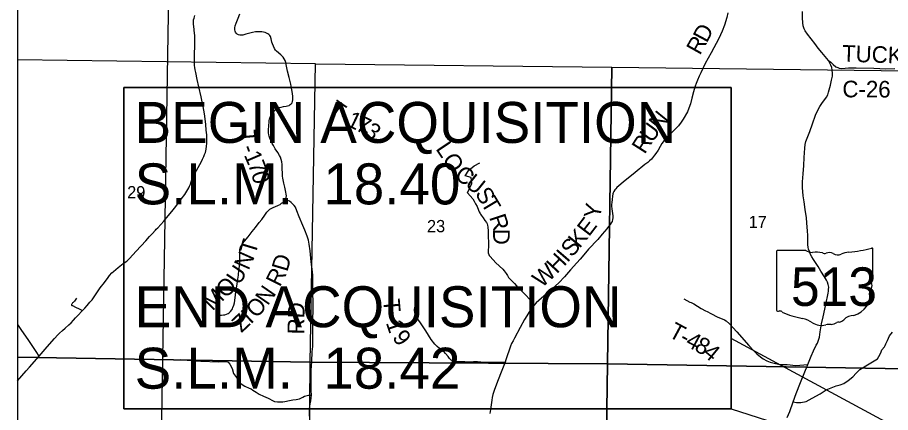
# Model space of a CAD drawing. Extents: x 0 to 34, y 0 to 22.
# Drawn here: x 2.1 to 5.085, y 17.307 to 18.658 of the extents above; entities that cross this region are included whole.
import ezdxf

# ---------------------------------------------------------------- set-up
doc = ezdxf.new("R2010")
doc.units = 0
for name, color, linetype in [('GM_X_Corporation', 7, 'Continuous'), ('GM_X_County_Road', 7, 'Continuous'), ('GM_X_County_Road_Text', 7, 'Continuous'), ('GM_X_Section_Text', 7, 'Continuous'), ('GM_X_State_Location', 7, 'Continuous'), ('GM_X_State_Route', 7, 'Continuous'), ('GM_X_State_Shield', 7, 'Continuous'), ('GM_X_Township_Road', 7, 'Continuous'), ('GM_X_Township_Road_Text', 7, 'Continuous'), ('GM_X_Township_Text', 7, 'Continuous'), ('SH_Data', 7, 'Continuous'), ('SH_Text', 7, 'Continuous')]:
    doc.layers.add(name, color=color, linetype=linetype)

msp = doc.modelspace()

# ---------------------------------------------------------------- linework, layer by layer
at = {"layer": 'GM_X_Corporation'}
for points in [[(2.1, 18.5128), (2.1, 17.4968), (3.1011, 17.4796), (3.1188, 18.4989)], [(3.1188, 18.4989), (4.1319, 18.4883), (4.1176, 17.4733), (3.1011, 17.4796)], [(4.1319, 18.4883), (5.1454, 18.4748), (5.1353, 17.4571), (4.1176, 17.4733)], [(2.1, 17.4968), (2.1, 16.4774), (3.0928, 16.4681), (3.1011, 17.4796)], [(3.1011, 17.4796), (4.1176, 17.4733), (4.1025, 16.4586), (3.0928, 16.4681)], [(4.1176, 17.4733), (5.1353, 17.4571), (5.122, 16.4496), (4.1025, 16.4586)]]:
    msp.add_lwpolyline(points, close=True, dxfattribs=at)
at = {"layer": 'GM_X_County_Road'}
for points in [[(2.5794, 17.939), (2.5999, 17.9616), (2.6041, 17.9664), (2.6281, 17.995), (2.6416, 18.0114), (2.6602, 18.0362), (2.6722, 18.0526), (2.6825, 18.0697), (2.6857, 18.075), (2.6883, 18.081), (2.6913, 18.0878), (2.6931, 18.0926), (2.695, 18.099), (2.697, 18.1066), (2.6991, 18.1112), (2.7017, 18.1167), (2.7178, 18.1452), (2.7237, 18.1556), (2.7277, 18.1629), (2.733, 18.1733), (2.7373, 18.1823), (2.7399, 18.189), (2.7425, 18.1966), (2.7449, 18.2073), (2.7466, 18.2183), (2.7475, 18.2264), (2.7474, 18.234), (2.7475, 18.2479), (2.7471, 18.2568), (2.7457, 18.2729), (2.7437, 18.2924), (2.7414, 18.3118), (2.7391, 18.3278), (2.7348, 18.3536), (2.7278, 18.3868), (2.7203, 18.4207), (2.7143, 18.4462), (2.7093, 18.4701), (2.7078, 18.4784), (2.7065, 18.4862), (2.7057, 18.4936), (2.7049, 18.5029), (2.7052, 18.5157), (2.7054, 18.5281), (2.7058, 18.5404), (2.7067, 18.5523), (2.7069, 18.5698), (2.7066, 18.5827), (2.7059, 18.5976), (2.7052, 18.6033), (2.7028, 18.6285), (2.7021, 18.6342), (2.7019, 18.6387), (2.7019, 18.6437), (2.7024, 18.6494), (2.7038, 18.6558), (2.7066, 18.6645)], [(4.5288, 18.6738), (4.5247, 18.6574), (4.517, 18.6315), (4.5092, 18.6111), (4.498, 18.5853), (4.4716, 18.5367), (4.4514, 18.5004), (4.4358, 18.469), (4.4306, 18.4575), (4.4246, 18.4438), (4.4201, 18.4323), (4.4168, 18.4225), (4.4113, 18.4032), (4.4058, 18.3816), (4.4007, 18.3629), (4.3954, 18.3476), (4.3903, 18.3356), (4.376, 18.3105), (4.3696, 18.3), (4.3597, 18.2873), (4.3513, 18.2783), (4.3367, 18.264), (4.3175, 18.2459), (4.3105, 18.237), (4.3033, 18.2265), (4.2969, 18.2162), (4.2899, 18.2047), (4.2826, 18.1929), (4.2784, 18.1866), (4.2676, 18.1735), (4.2612, 18.1675), (4.2552, 18.1625), (4.2451, 18.1547), (4.2118, 18.1281), (4.1934, 18.1135), (4.1781, 18.1009), (4.1495, 18.0763), (4.1461, 18.0725), (4.1422, 18.0682), (4.1392, 18.0634), (4.1369, 18.0581), (4.136, 18.0546), (4.1347, 18.0473), (4.1331, 18.0356), (4.1318, 18.0251), (4.1314, 18.0179), (4.1314, 18.0126), (4.1322, 18.0032), (4.1344, 17.9874), (4.135, 17.9801), (4.1353, 17.9731), (4.1344, 17.9668), (4.1326, 17.9607), (4.1303, 17.9558), (4.1266, 17.9506), (4.1209, 17.9428), (4.1146, 17.9353), (4.0988, 17.9168), (4.0836, 17.8992), (4.0526, 17.8655), (4.0415, 17.8527), (4.0233, 17.8317), (4.0125, 17.8196), (3.991, 17.7949), (3.9703, 17.7707), (3.9508, 17.7512), (3.9287, 17.7314), (3.9076, 17.7124), (3.8916, 17.6982), (3.8822, 17.6898), (3.8736, 17.6821), (3.8658, 17.6734), (3.8603, 17.6662), (3.8552, 17.6592), (3.8486, 17.6495), (3.8412, 17.6374), (3.834, 17.6258), (3.8182, 17.5981), (3.7995, 17.5617), (3.7945, 17.552), (3.789, 17.5428), (3.7853, 17.5342), (3.7695, 17.4874), (3.7668, 17.4795), (3.7561, 17.4506), (3.7416, 17.4136), (3.7294, 17.3831), (3.7253, 17.3692), (3.723, 17.3587), (3.7213, 17.3498), (3.7171, 17.3181), (3.715, 17.3038)], [(4.8728, 18.5108), (4.881, 18.5054), (4.8889, 18.4975), (4.8974, 18.4895), (4.9044, 18.4866), (4.9096, 18.4847), (4.9164, 18.4838), (4.9293, 18.485), (4.9416, 18.4856), (4.9668, 18.4855), (5.0278, 18.4839), (5.048, 18.4834), (5.0692, 18.4821), (5.0991, 18.4833)], [(2.1, 17.4156), (2.1298, 17.4495), (2.1411, 17.4622), (2.174, 17.5004), (2.1813, 17.5085), (2.2019, 17.5324), (2.2261, 17.56), (2.2382, 17.5733), (2.2438, 17.5788), (2.254, 17.5881), (2.2631, 17.5962), (2.2756, 17.6074), (2.2832, 17.6145), (2.2914, 17.6227), (2.2989, 17.6307), (2.3068, 17.6391), (2.3215, 17.6547), (2.3228, 17.6563), (2.33, 17.6641), (2.3387, 17.6736), (2.3478, 17.6841), (2.355, 17.693), (2.3733, 17.7197), (2.3779, 17.7263), (2.383, 17.7333), (2.3973, 17.7518), (2.41, 17.7695), (2.4152, 17.7762), (2.4225, 17.7844), (2.428, 17.7897), (2.4362, 17.7963), (2.4448, 17.8031), (2.4619, 17.8163), (2.4734, 17.8252), (2.4829, 17.8339), (2.5063, 17.8586), (2.5384, 17.8944), (2.5519, 17.9088), (2.5602, 17.9181), (2.5724, 17.9312), (2.5746, 17.9338), (2.5794, 17.939)]]:
    msp.add_lwpolyline(points, dxfattribs=at)
at = {"layer": 'GM_X_State_Route'}
msp.add_lwpolyline([(4.7319, 17.2902), (4.7401, 17.3107), (4.7518, 17.3441), (4.7623, 17.372), (4.7769, 17.4097), (4.8024, 17.4712), (4.8133, 17.4995), (4.8216, 17.5186), (4.8311, 17.5373), (4.8347, 17.5449), (4.8385, 17.5545), (4.8415, 17.5646), (4.8433, 17.5741), (4.8443, 17.5827), (4.8491, 17.6101), (4.8545, 17.6342), (4.8637, 17.6765), (4.8713, 17.7153), (4.8724, 17.7218), (4.8732, 17.7284), (4.8735, 17.7362), (4.8718, 17.7453), (4.8693, 17.7529), (4.8662, 17.76), (4.8589, 17.7713), (4.8466, 17.7903), (4.837, 17.806), (4.8213, 17.8301), (4.8161, 17.8394), (4.8113, 17.8481), (4.8076, 17.8573), (4.8047, 17.866), (4.8034, 17.8723), (4.8023, 17.881), (4.8019, 17.8913), (4.8021, 17.9131), (4.8014, 17.9277), (4.7989, 17.9562), (4.7978, 17.973), (4.7931, 18.0019), (4.7898, 18.027), (4.7862, 18.0482), (4.784, 18.077), (4.7839, 18.0959), (4.7858, 18.1232), (4.7883, 18.1521), (4.79, 18.1786), (4.7915, 18.2111), (4.7931, 18.2241), (4.7955, 18.2341), (4.8084, 18.2682), (4.8176, 18.2942), (4.8287, 18.3239), (4.8356, 18.3386), (4.8426, 18.3536), (4.8502, 18.3642), (4.8662, 18.3852), (4.8701, 18.3936), (4.8729, 18.4028), (4.8792, 18.4262), (4.8834, 18.4429), (4.8861, 18.4569), (4.8861, 18.4672), (4.8851, 18.4781), (4.8839, 18.4867), (4.8809, 18.495), (4.8728, 18.5108), (4.8495, 18.5378), (4.8377, 18.5525), (4.8257, 18.5682), (4.8011, 18.6001), (4.7933, 18.6118), (4.789, 18.6193), (4.7857, 18.6295), (4.7845, 18.6392), (4.7842, 18.6565), (4.7836, 18.6785)], dxfattribs=at)
at = {"layer": 'GM_X_State_Shield'}
for p, q in [((4.6949, 17.8577), (4.6949, 17.6576)), ((4.7947, 17.8612), (4.6982, 17.8612)), ((5.0245, 17.7615), (5.0245, 17.8661)), ((5.0245, 17.7615), (5.0245, 17.7615))]:
    msp.add_line(p, q, dxfattribs=at)
for centre, major_axis, start_param, end_param in [((4.6987, 17.8582), (0.00382, 0), 1.712693, 3.28349), ((4.8177, 17.8844), (0.037, 0), 4.042523, 4.731795), ((4.8299, 17.7488), (0.133, 0), 1.404758, 1.657858), ((4.8601, 17.8592), (0.0107, 0), 3.836095, 5.185415), ((4.8758, 17.8361), (0.0222, 0), 0.950623, 2.079405), ((4.9045, 17.8678), (0.0267, 0), 4.081561, 5.145723), ((4.9517, 17.8001), (0.0703, 0), 1.699011, 2.107814), ((4.9071, 18.134), (0.3495, 0), 4.814394, 5.042369), ((5.0208, 17.8666), (0.00367, 0), 6.141152, 7.989035), ((5.0206, 17.761), (0.00393, 0), 5.05454, 6.418171), ((5.0376, 17.7176), (0.0248, 0), 2.387724, 3.262537), ((5.0237, 17.7538), (0.00568, 0), 1.883978, 3.671073), ((4.9875, 17.7405), (0.0341, 0), 5.934695, 6.695948), ((4.9267, 17.7043), (0.0874, 0), 5.101752, 6.440018), ((4.6987, 17.6572), (0.00385, 0), 3.00124, 4.508301), ((4.6993, 17.6777), (0.0294, 0), 4.665946, 4.897461), ((4.7053, 17.6461), (0.0106, 0), 0.519207, 1.627899), ((4.8391, 17.8259), (0.2524, 0), 4.195997, 4.488961), ((4.7639, 17.5677), (0.079, 0), 0.823519, 1.323587), ((4.8493, 17.6451), (0.0501, 0), 4.026481, 4.996735), ((4.8819, 17.6301), (0.0267, 0), 4.691044, 5.507374), ((4.9061, 17.6107), (0.00752, 0), 1.147584, 2.315152), ((4.9029, 17.6382), (0.0282, 0), 4.937069, 5.64225), ((4.9635, 17.6014), (0.0479, 0), 1.647645, 2.488434), ((4.8783, 17.5759), (0.0412, 0), 1.495662, 1.94098)]:
    msp.add_ellipse(centre, major_axis=major_axis, ratio=0.8, start_param=start_param, end_param=end_param, dxfattribs=at)
at = {"layer": 'GM_X_Township_Road'}
for points in [[(2.7805, 17.6406), (2.7843, 17.6403), (2.7916, 17.6404), (2.7979, 17.6405), (2.8049, 17.641), (2.8092, 17.6416), (2.8149, 17.6431), (2.8202, 17.6455), (2.824, 17.6481), (2.8264, 17.65), (2.8288, 17.6528), (2.833, 17.6585), (2.8351, 17.6622), (2.8367, 17.6662), (2.8393, 17.6741), (2.8417, 17.6824), (2.8432, 17.6903), (2.8453, 17.7102), (2.8465, 17.7205), (2.8496, 17.7397), (2.8536, 17.7631), (2.8554, 17.7769), (2.8558, 17.7809), (2.8569, 17.7918), (2.8587, 17.8073), (2.86, 17.8195), (2.8605, 17.8291), (2.8606, 17.845), (2.8603, 17.853), (2.8604, 17.8606), (2.8606, 17.8644), (2.8616, 17.8696), (2.8628, 17.8735), (2.8646, 17.8778), (2.8668, 17.8811), (2.8694, 17.885), (2.8758, 17.8929), (2.8887, 17.9084), (2.9027, 17.9259), (2.9137, 17.9397), (2.9268, 17.9564), (2.9353, 17.9676), (2.9459, 17.9823), (2.9528, 17.9921), (2.9575, 17.9973), (2.9632, 18.0021), (2.9674, 18.0046), (2.9724, 18.0071), (2.9842, 18.0123), (2.9883, 18.0141), (2.9926, 18.0163), (2.9976, 18.019), (3.0028, 18.0225), (3.0107, 18.0281), (3.0146, 18.0324), (3.0166, 18.0353), (3.018, 18.0383), (3.0188, 18.0427), (3.0194, 18.0479), (3.019, 18.0541), (3.0179, 18.0611), (3.0139, 18.0779), (3.0111, 18.0911), (3.0078, 18.1087), (3.0065, 18.1157), (3.0057, 18.1242), (3.0053, 18.141), (3.0053, 18.1472), (3.0048, 18.1557), (3.0041, 18.1638), (3.0021, 18.1726), (2.9993, 18.1802), (2.9961, 18.1859), (2.9898, 18.1959), (2.9816, 18.2087), (2.9751, 18.2198), (2.9711, 18.2269), (2.9675, 18.2344), (2.9625, 18.2453), (2.9606, 18.2515), (2.9594, 18.2564), (2.9581, 18.2638), (2.958, 18.269), (2.9583, 18.2736), (2.9603, 18.3012), (2.9609, 18.3061), (2.9621, 18.3105), (2.9633, 18.3144), (2.965, 18.3193), (2.9681, 18.3251), (2.9712, 18.33), (2.9751, 18.3348), (2.9785, 18.3389), (2.9829, 18.3428), (2.9873, 18.3456), (2.9917, 18.3481), (2.9961, 18.3499), (3.0016, 18.3515), (3.0096, 18.3533), (3.0183, 18.3547), (3.0235, 18.3559), (3.0286, 18.3574), (3.0327, 18.3597), (3.0363, 18.3629), (3.0386, 18.3661), (3.0407, 18.3705), (3.0419, 18.3766), (3.0418, 18.3833), (3.0415, 18.389), (3.0405, 18.3962), (3.0397, 18.4044), (3.0372, 18.4166), (3.0342, 18.4303), (3.0287, 18.4525), (3.0236, 18.4738), (3.0192, 18.4965), (3.0174, 18.504), (3.0151, 18.5104), (3.0118, 18.5165), (3.0085, 18.5219), (3.0051, 18.5256), (3.0003, 18.5301), (2.9854, 18.543), (2.9821, 18.5465), (2.9791, 18.5512), (2.9749, 18.5599), (2.9716, 18.5677), (2.9698, 18.5732), (2.9685, 18.5792), (2.9669, 18.5852), (2.9649, 18.5926), (2.9623, 18.5965), (2.9592, 18.5997), (2.9555, 18.6023), (2.9516, 18.6042), (2.9465, 18.606), (2.9352, 18.6082), (2.9261, 18.609), (2.9198, 18.6089), (2.9142, 18.6088), (2.9041, 18.6069), (2.8947, 18.6043), (2.8803, 18.6003), (2.8706, 18.5977), (2.8659, 18.5969), (2.8608, 18.5967), (2.8554, 18.5981), (2.8515, 18.6004), (2.8481, 18.6037), (2.8456, 18.6075), (2.8442, 18.6114), (2.8432, 18.6159), (2.8432, 18.6221), (2.8445, 18.6295), (2.8475, 18.6383), (2.8547, 18.655), (2.8608, 18.6698)], [(3.6387, 18.058), (3.6538, 18.0901), (3.6508, 18.1102), (3.6307, 18.1162), (3.6427, 18.1353), (3.6618, 18.1504), (3.6809, 18.1614)], [(3.0984, 17.2954), (3.0983, 17.3106), (3.0988, 17.3201), (3.0994, 17.3279), (3.1006, 17.3376), (3.1026, 17.3467), (3.1043, 17.3574), (3.1053, 17.3666), (3.1046, 17.3831), (3.1038, 17.4269), (3.1037, 17.4521), (3.1064, 17.4819), (3.108, 17.5146), (3.1098, 17.533), (3.1099, 17.567), (3.1096, 17.5905), (3.1096, 17.6291), (3.1106, 17.6554), (3.1109, 17.6823), (3.1097, 17.7173), (3.1099, 17.7412), (3.1102, 17.7509), (3.11, 17.7604), (3.1095, 17.7755), (3.1084, 17.7881), (3.1045, 17.8225), (3.102, 17.8473), (3.1011, 17.8602), (3.0975, 17.8829), (3.0949, 17.8964), (3.0903, 17.9104), (3.0821, 17.9306), (3.0757, 17.9464), (3.0635, 17.9759), (3.0555, 17.9964), (3.05, 18.0089), (3.046, 18.0151), (3.043, 18.0186), (3.0401, 18.021), (3.0353, 18.0255), (3.0295, 18.03), (3.0238, 18.0323), (3.0202, 18.0324), (3.0167, 18.0317), (3.0107, 18.0281)], [(3.6387, 18.058), (3.6564, 18.0379), (3.6608, 18.0296), (3.6655, 18.0209), (3.6719, 18.0113), (3.6762, 17.9991), (3.6787, 17.9935), (3.6814, 17.9881), (3.6831, 17.9857)], [(3.6831, 17.9857), (3.6854, 17.9825), (3.6919, 17.9729), (3.6984, 17.964), (3.703, 17.9571), (3.7054, 17.9521), (3.7069, 17.9476), (3.7082, 17.9412), (3.7091, 17.929), (3.7091, 17.9146), (3.7101, 17.8829), (3.7098, 17.8733), (3.7089, 17.8625), (3.7088, 17.8533), (3.711, 17.8474), (3.7132, 17.844), (3.7158, 17.8407), (3.7359, 17.8195), (3.7593, 17.797), (3.7639, 17.7921), (3.7679, 17.7868), (3.7706, 17.7826), (3.7753, 17.7756), (3.7791, 17.7688), (3.7817, 17.7654), (3.7874, 17.7596), (3.7992, 17.748), (3.8061, 17.7409), (3.8094, 17.7361), (3.8168, 17.7288), (3.8262, 17.7199), (3.8394, 17.7071), (3.8495, 17.6961), (3.8557, 17.6885), (3.8606, 17.6824), (3.8619, 17.6783), (3.8625, 17.6741), (3.8603, 17.6662)], [(2.3016, 17.6979), (2.2975, 17.6917), (2.2946, 17.6884), (2.2923, 17.6861), (2.2901, 17.684), (2.2884, 17.6825), (2.2871, 17.6805), (2.2859, 17.6783), (2.2852, 17.6767), (2.2849, 17.6757), (2.2849, 17.6745), (2.2857, 17.6738), (2.288, 17.6729), (2.2988, 17.6678), (2.3107, 17.6622), (2.3174, 17.658), (2.3215, 17.6547)], [(4.3777, 17.6959), (4.3992, 17.6844), (4.4031, 17.6833), (4.4122, 17.6784), (4.4376, 17.6632), (4.4522, 17.6551), (4.4574, 17.653), (4.4702, 17.6454), (4.4948, 17.6337), (4.5094, 17.6279), (4.517, 17.6247), (4.5231, 17.6211), (4.5345, 17.6103), (4.5461, 17.5983), (4.5596, 17.5831), (4.6002, 17.5367), (4.6174, 17.5181), (4.6277, 17.5078), (4.6399, 17.4982), (4.6499, 17.4911), (4.6616, 17.4841), (4.6736, 17.4794), (4.687, 17.4757), (4.7019, 17.4729), (4.7145, 17.4721), (4.7319, 17.4716), (4.761, 17.4682), (4.8024, 17.4712)], [(3.7668, 17.4795), (3.7409, 17.4788), (3.7165, 17.4786), (3.6957, 17.4787), (3.6842, 17.4795), (3.6725, 17.4805), (3.6592, 17.4808), (3.6526, 17.4798), (3.6457, 17.4797), (3.6296, 17.4803), (3.6105, 17.4804), (3.5983, 17.4811), (3.5927, 17.4817), (3.5871, 17.4836), (3.5825, 17.4869), (3.5771, 17.4924), (3.572, 17.4988), (3.5635, 17.5095), (3.5571, 17.5155), (3.549, 17.5214), (3.5423, 17.5265), (3.5351, 17.5328), (3.5269, 17.5413), (3.5145, 17.5575), (3.4962, 17.5864), (3.4755, 17.6173), (3.4676, 17.6282), (3.4636, 17.6348), (3.4611, 17.6401), (3.4589, 17.6484), (3.4574, 17.6588), (3.458, 17.6681)], [(2.174, 17.5004), (2.1639, 17.5163), (2.1388, 17.5538), (2.1128, 17.5912), (2.1009, 17.6079), (2.1, 17.6091)], [(5.0405, 17.4909), (5.0451, 17.4988), (5.0515, 17.5113), (5.0556, 17.5213), (5.0639, 17.5318), (5.0667, 17.5366), (5.0686, 17.5424), (5.0747, 17.5535), (5.0811, 17.5695), (5.092, 17.5818)], [(2.6588, 17.489), (2.6641, 17.4875), (2.7274, 17.4827), (2.7869, 17.4806), (2.8059, 17.4816), (2.8146, 17.4815), (2.8206, 17.4792), (2.8263, 17.4723), (2.8337, 17.4582), (2.8389, 17.4407), (2.8488, 17.4268), (2.8549, 17.4174), (2.8581, 17.4124), (2.8621, 17.408), (2.8681, 17.4028), (2.877, 17.3975), (2.8917, 17.391), (2.8986, 17.3879), (2.9043, 17.3842), (2.9157, 17.3766), (2.9269, 17.37), (2.9412, 17.3637), (2.9567, 17.3562), (2.9746, 17.3474), (2.9793, 17.3453), (2.989, 17.3441), (2.9982, 17.3437), (3.0067, 17.3441), (3.0142, 17.3453), (3.0298, 17.3485), (3.0419, 17.3505), (3.0531, 17.352), (3.0581, 17.3527), (3.064, 17.3541), (3.0691, 17.3569), (3.0751, 17.3599), (3.0812, 17.3628), (3.086, 17.3647), (3.0907, 17.3661), (3.0954, 17.3671), (3.1001, 17.3671), (3.1053, 17.3666)], [(4.7518, 17.3441), (4.7631, 17.3414), (4.7779, 17.3414), (4.7968, 17.3455), (4.8173, 17.3562), (4.8445, 17.3718), (4.8642, 17.3849), (4.8823, 17.3923), (4.8987, 17.3981), (4.9127, 17.4022), (4.925, 17.4071), (4.9398, 17.417), (4.9554, 17.4293), (4.9678, 17.4425), (4.9801, 17.454), (5.0118, 17.4735), (5.0405, 17.4909)]]:
    msp.add_lwpolyline(points, dxfattribs=at)
at = {"layer": 'GM_X_Township_Text'}
msp.add_line((2.1, 19.1775), (2.1, 16.4804), dxfattribs=at)
msp.add_lwpolyline([(2.6249, 19.1744), (2.6223, 19.0497), (2.622, 19.0358), (2.6202, 18.9481), (2.604, 17.9706), (2.6039, 17.9669), (2.5791, 16.4754), (2.4938, 16.4762), (2.1, 16.4804), (2.1, 14.1), (7.1227, 14.1)], dxfattribs=at)
at = {"layer": 'SH_Data'}
msp.add_line((2.1, 20.9), (2.1, 14.1), dxfattribs=at)
at = {"layer": 'SH_Text'}
for points in [[(4.5397, 18.4189), (2.4638, 18.4189), (2.4638, 17.32), (4.5397, 17.32)], [(2.4638, 18.4189), (4.5397, 18.4189), (4.5397, 17.32), (2.4638, 17.32)], [(5.6379, 16.9679), (4.5397, 17.56), (4.5397, 17.32)]]:
    msp.add_lwpolyline(points, close=True, dxfattribs=at)

# ---------------------------------------------------------------- texts
at = {"layer": 'GM_X_County_Road_Text'}
for s, height, rotation, p in [('D', 0.0568, 62.048, (4.4566, 18.5683)), ('R', 0.0568, 60.6516, (4.433, 18.5263)), ('TUCKAHOE', 0.05682, 358.1241, (4.9184, 18.5069)), ('C-26', 0.05682, 359.6571, (4.9202, 18.3849)), ('N', 0.0568, 51.1217, (4.2977, 18.2664)), ('U', 0.0568, 54.0947, (4.2689, 18.2265)), ('R', 0.0568, 57.4932, (4.2443, 18.1879)), ('Y', 0.0568, 80.2604, (4.0914, 17.9673)), ('E', 0.0568, 52.6032, (4.0537, 17.9063)), ('K', 0.0568, 51.3297, (4.0216, 17.8662)), ('S', 0.0568, 49.6738, (3.9957, 17.8356)), ('H', 0.0568, 46.8848, (3.9443, 17.7792)), ('I', 0.0568, 49.2491, (3.9802, 17.8176)), ('W', 0.0568, 42.6321, (3.8926, 17.7313))]:
    msp.add_text(s, height=height, rotation=rotation, dxfattribs=at).set_placement(p)
at = {"layer": 'GM_X_Section_Text'}
for s, p in [('29', (2.475, 18.0395)), ('17', (4.5996, 17.9376)), ('23', (3.5, 17.9237))]:
    msp.add_text(s, height=0.04186, rotation=0, dxfattribs=at).set_placement(p)
at = {"layer": 'GM_X_State_Location'}
msp.add_text('513', height=0.000189, rotation=0, dxfattribs=at).set_placement((4.7891, 17.7306))
for s in ['s', 'r']:
    msp.add_text(s, height=0.000189, dxfattribs=at).set_placement((4.856, 17.7444))
at = {"layer": 'GM_X_State_Shield'}
msp.add_text('513', height=0.13184, dxfattribs=at).set_placement((4.7444, 17.6717))
at = {"layer": 'GM_X_Township_Road_Text'}
for s, height, rotation, p in [('T', 0.0568, 325.2674, (3.1587, 18.3318)), ('1', 0.0568, 333.8217, (3.221, 18.2899)), ('-', 0.0568, 326.1542, (3.1944, 18.3071)), ('7', 0.0568, 332.9742, (3.2522, 18.2746)), ('T', 0.0568, 275.2573, (2.8565, 18.2707)), ('3', 0.0568, 320.7794, (3.2807, 18.2604)), ('-', 0.0568, 290.4386, (2.864, 18.2124)), ('L', 0.0568, 303.866, (3.5281, 18.209)), ('1', 0.0568, 293.2345, (2.8733, 18.1878)), ('O', 0.0568, 299.1937, (3.5512, 18.1747)), ('7', 0.0568, 291.4149, (2.8869, 18.156)), ('0', 0.0568, 283.9706, (2.8991, 18.1253)), ('C', 0.0568, 320.9281, (3.5906, 18.1131)), ('U', 0.0568, 321.1905, (3.6271, 18.0836)), ('S', 0.0568, 301.614, (3.6627, 18.056)), ('T', 0.0568, 301.0064, (3.6827, 18.0235)), ('R', 0.0568, 288.2239, (3.7121, 17.9751)), ('D', 0.0568, 270.1603, (3.726, 17.9355)), ('T', 0.0568, 73.2772, (2.9131, 17.8442)), ('N', 0.0568, 66.0455, (2.8901, 17.7912)), ('D', 0.0568, 73.6408, (3.0223, 17.7863)), ('U', 0.0568, 56.1315, (2.857, 17.7403)), ('R', 0.0568, 63.2907, (2.9972, 17.7342)), ('O', 0.0568, 42.3278, (2.8103, 17.6953)), ('M', 0.0568, 44.2585, (2.7665, 17.6526)), ('N', 0.0568, 55.4169, (2.9557, 17.6705)), ('O', 0.0568, 48.0129, (2.9173, 17.6271)), ('RD', 0.05682, 89.0127, (3.0801, 17.574)), ('T', 0.0568, 274.685, (3.35, 17.6943)), ('Z', 0.0568, 43.0359, (2.8656, 17.5781)), ('I', 0.0568, 43.7437, (2.8972, 17.6076)), ('-', 0.0568, 276.2026, (3.3536, 17.6503)), ('1', 0.0568, 288.4214, (3.359, 17.6143)), ('T', 0.0568, 331.6734, (4.3224, 17.5685)), ('9', 0.0568, 306.9217, (3.3793, 17.5634)), ('-', 0.0568, 331.6718, (4.3598, 17.5483)), ('4', 0.0568, 331.6101, (4.3803, 17.5373)), ('8', 0.0568, 331.3796, (4.411, 17.5207)), ('4', 0.0568, 320.299, (4.4394, 17.5055))]:
    msp.add_text(s, height=height, rotation=rotation, dxfattribs=at).set_placement(p)
at = {"layer": 'SH_Text'}
for s, p in [('BEGIN ACQUISITION', (2.5007, 18.2289)), ('S.L.M.  18.40', (2.5007, 18.0189)), ('END ACQUISITION', (2.5007, 17.5989)), ('S.L.M.  18.42', (2.5007, 17.3889))]:
    msp.add_text(s, height=0.14, dxfattribs=at).set_placement(p)

doc.saveas('drawing.dxf')
